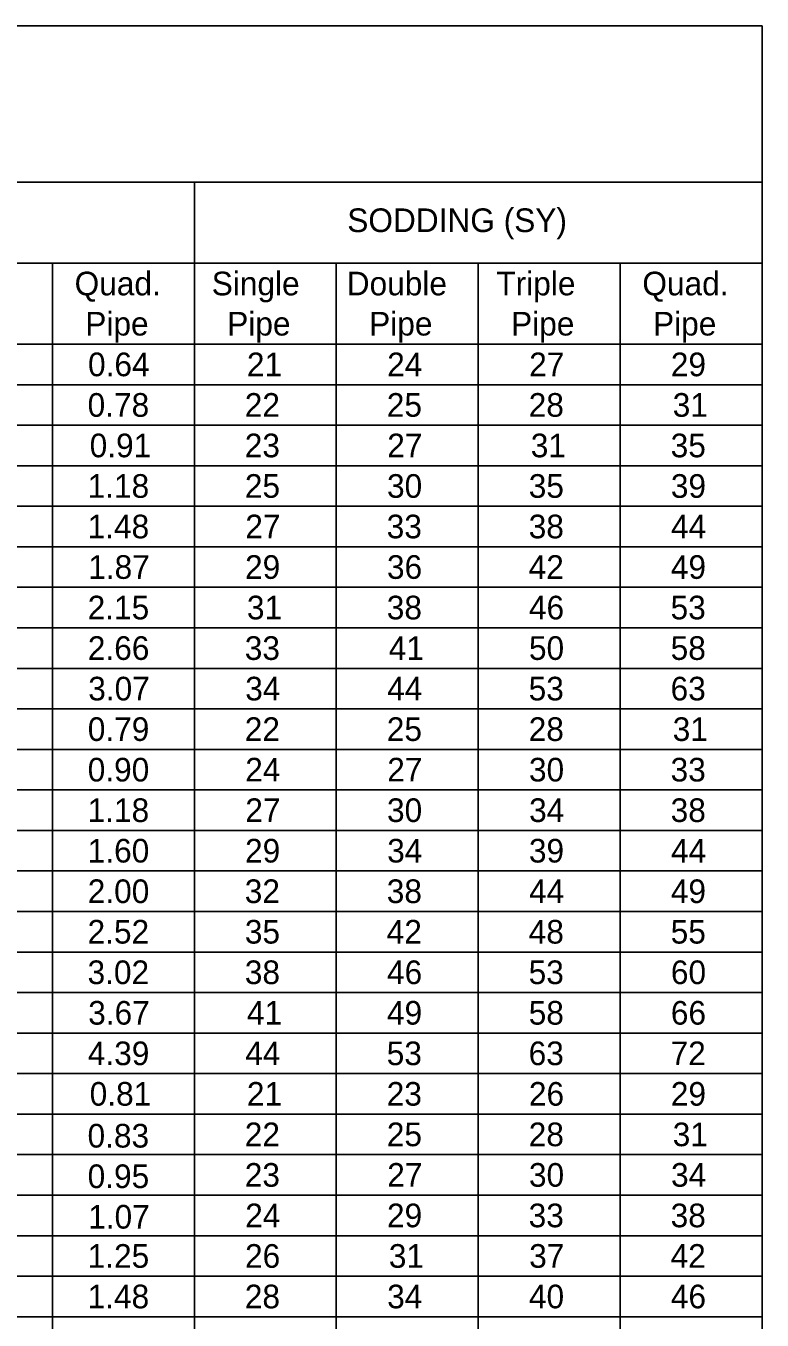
# Model space of a CAD drawing. Extents: x 1.7 to 14.4, y 0 to 7.8.
# Drawn here: x 11.282 to 13.46, y 3.92 to 7.752 of the extents above; entities that cross this region are included whole.
import ezdxf

# ---------------------------------------------------------------- set-up
doc = ezdxf.new("R2010")
doc.units = 0
doc.layers.add('Table', color=7, linetype='Continuous')

msp = doc.modelspace()

# ---------------------------------------------------------------- linework, layer by layer
at = {"layer": 'Table'}
msp.add_line((1.94, 7.7524), (13.46, 7.7524), dxfattribs=at)
for points in [[(13.46, 7.7524), (13.46, 7.17), (13.46, 6.81), (13.46, 6.69), (13.46, 6.57), (13.46, 6.45), (13.46, 6.33), (13.46, 6.21), (13.46, 6.09), (13.46, 5.97), (13.46, 5.85), (13.46, 5.73), (13.46, 5.61), (13.46, 5.49), (13.46, 5.37), (13.46, 5.25), (13.46, 5.13), (13.46, 5.01), (13.46, 4.89), (13.46, 4.77), (13.46, 4.65), (13.46, 4.53), (13.46, 4.41), (13.46, 4.29), (13.46, 4.17), (13.46, 4.05), (13.46, 3.93), (13.46, 3.81)], [(13.46, 7.29), (11.78, 7.29), (10.1, 7.29), (8.42, 7.29), (8.06, 7.29), (6.38, 7.29), (6.02, 7.29), (5.66, 7.29), (5.3, 7.29), (4.94, 7.29), (4.52, 7.29), (4.04, 7.29), (3.62, 7.29), (3.2, 7.29), (2.9, 7.29), (2.6, 7.29), (2.3, 7.29), (1.94, 7.29)], [(11.78, 7.29), (11.78, 6.81), (11.78, 6.69), (11.78, 6.57), (11.78, 6.45), (11.78, 6.33), (11.78, 6.21), (11.78, 6.09), (11.78, 5.97), (11.78, 5.85), (11.78, 5.73), (11.78, 5.61), (11.78, 5.49), (11.78, 5.37), (11.78, 5.25), (11.78, 5.13), (11.78, 5.01), (11.78, 4.89), (11.78, 4.77), (11.78, 4.65), (11.78, 4.53), (11.78, 4.41), (11.78, 4.29), (11.78, 4.17), (11.78, 4.05), (11.78, 3.93), (11.78, 3.81)], [(8.42, 7.05), (8.84, 7.05), (9.26, 7.05), (9.68, 7.05), (10.1, 7.05), (10.52, 7.05), (10.94, 7.05), (11.36, 7.05), (11.78, 7.05), (12.2, 7.05), (12.62, 7.05), (13.04, 7.05), (13.46, 7.05)], [(11.36, 7.05), (11.36, 6.81), (11.36, 6.69), (11.36, 6.57), (11.36, 6.45), (11.36, 6.33), (11.36, 6.21), (11.36, 6.09), (11.36, 5.97), (11.36, 5.85), (11.36, 5.73), (11.36, 5.61), (11.36, 5.49), (11.36, 5.37), (11.36, 5.25), (11.36, 5.13), (11.36, 5.01), (11.36, 4.89), (11.36, 4.77), (11.36, 4.65), (11.36, 4.53), (11.36, 4.41), (11.36, 4.29), (11.36, 4.17), (11.36, 4.05), (11.36, 3.93), (11.36, 3.81)], [(12.2, 7.05), (12.2, 6.81), (12.2, 6.69), (12.2, 6.57), (12.2, 6.45), (12.2, 6.33), (12.2, 6.21), (12.2, 6.09), (12.2, 5.97), (12.2, 5.85), (12.2, 5.73), (12.2, 5.61), (12.2, 5.49), (12.2, 5.37), (12.2, 5.25), (12.2, 5.13), (12.2, 5.01), (12.2, 4.89), (12.2, 4.77), (12.2, 4.65), (12.2, 4.53), (12.2, 4.41), (12.2, 4.29), (12.2, 4.17), (12.2, 4.05), (12.2, 3.93), (12.2, 3.81)], [(12.62, 7.05), (12.62, 6.81), (12.62, 6.69), (12.62, 6.57), (12.62, 6.45), (12.62, 6.33), (12.62, 6.21), (12.62, 6.09), (12.62, 5.97), (12.62, 5.85), (12.62, 5.73), (12.62, 5.61), (12.62, 5.49), (12.62, 5.37), (12.62, 5.25), (12.62, 5.13), (12.62, 5.01), (12.62, 4.89), (12.62, 4.77), (12.62, 4.65), (12.62, 4.53), (12.62, 4.41), (12.62, 4.29), (12.62, 4.17), (12.62, 4.05), (12.62, 3.93), (12.62, 3.81)], [(13.04, 7.05), (13.04, 6.81), (13.04, 6.69), (13.04, 6.57), (13.04, 6.45), (13.04, 6.33), (13.04, 6.21), (13.04, 6.09), (13.04, 5.97), (13.04, 5.85), (13.04, 5.73), (13.04, 5.61), (13.04, 5.49), (13.04, 5.37), (13.04, 5.25), (13.04, 5.13), (13.04, 5.01), (13.04, 4.89), (13.04, 4.77), (13.04, 4.65), (13.04, 4.53), (13.04, 4.41), (13.04, 4.29), (13.04, 4.17), (13.04, 4.05), (13.04, 3.93), (13.04, 3.81)], [(8.06, 6.81), (8.42, 6.81), (8.84, 6.81), (9.26, 6.81), (9.68, 6.81), (10.1, 6.81), (10.52, 6.81), (10.94, 6.81), (11.36, 6.81), (11.78, 6.81), (12.2, 6.81), (12.62, 6.81), (13.04, 6.81), (13.46, 6.81)], [(8.06, 6.69), (8.42, 6.69), (8.84, 6.69), (9.26, 6.69), (9.68, 6.69), (10.1, 6.69), (10.52, 6.69), (10.94, 6.69), (11.36, 6.69), (11.78, 6.69), (12.2, 6.69), (12.62, 6.69), (13.04, 6.69), (13.46, 6.69)], [(8.06, 6.57), (8.42, 6.57), (8.84, 6.57), (9.26, 6.57), (9.68, 6.57), (10.1, 6.57), (10.52, 6.57), (10.94, 6.57), (11.36, 6.57), (11.78, 6.57), (12.2, 6.57), (12.62, 6.57), (13.04, 6.57), (13.46, 6.57)], [(8.06, 6.45), (8.42, 6.45), (8.84, 6.45), (9.26, 6.45), (9.68, 6.45), (10.1, 6.45), (10.52, 6.45), (10.94, 6.45), (11.36, 6.45), (11.78, 6.45), (12.2, 6.45), (12.62, 6.45), (13.04, 6.45), (13.46, 6.45)], [(8.06, 6.33), (8.42, 6.33), (8.84, 6.33), (9.26, 6.33), (9.68, 6.33), (10.1, 6.33), (10.52, 6.33), (10.94, 6.33), (11.36, 6.33), (11.78, 6.33), (12.2, 6.33), (12.62, 6.33), (13.04, 6.33), (13.46, 6.33)], [(8.06, 6.21), (8.42, 6.21), (8.84, 6.21), (9.26, 6.21), (9.68, 6.21), (10.1, 6.21), (10.52, 6.21), (10.94, 6.21), (11.36, 6.21), (11.78, 6.21), (12.2, 6.21), (12.62, 6.21), (13.04, 6.21), (13.46, 6.21)], [(8.06, 6.09), (8.42, 6.09), (8.84, 6.09), (9.26, 6.09), (9.68, 6.09), (10.1, 6.09), (10.52, 6.09), (10.94, 6.09), (11.36, 6.09), (11.78, 6.09), (12.2, 6.09), (12.62, 6.09), (13.04, 6.09), (13.46, 6.09)], [(8.06, 5.97), (8.42, 5.97), (8.84, 5.97), (9.26, 5.97), (9.68, 5.97), (10.1, 5.97), (10.52, 5.97), (10.94, 5.97), (11.36, 5.97), (11.78, 5.97), (12.2, 5.97), (12.62, 5.97), (13.04, 5.97), (13.46, 5.97)], [(8.06, 5.85), (8.42, 5.85), (8.84, 5.85), (9.26, 5.85), (9.68, 5.85), (10.1, 5.85), (10.52, 5.85), (10.94, 5.85), (11.36, 5.85), (11.78, 5.85), (12.2, 5.85), (12.62, 5.85), (13.04, 5.85), (13.46, 5.85)], [(8.06, 5.73), (8.42, 5.73), (8.84, 5.73), (9.26, 5.73), (9.68, 5.73), (10.1, 5.73), (10.52, 5.73), (10.94, 5.73), (11.36, 5.73), (11.78, 5.73), (12.2, 5.73), (12.62, 5.73), (13.04, 5.73), (13.46, 5.73)], [(8.06, 5.61), (8.42, 5.61), (8.84, 5.61), (9.26, 5.61), (9.68, 5.61), (10.1, 5.61), (10.52, 5.61), (10.94, 5.61), (11.36, 5.61), (11.78, 5.61), (12.2, 5.61), (12.62, 5.61), (13.04, 5.61), (13.46, 5.61)], [(8.06, 5.49), (8.42, 5.49), (8.84, 5.49), (9.26, 5.49), (9.68, 5.49), (10.1, 5.49), (10.52, 5.49), (10.94, 5.49), (11.36, 5.49), (11.78, 5.49), (12.2, 5.49), (12.62, 5.49), (13.04, 5.49), (13.46, 5.49)], [(8.06, 5.37), (8.42, 5.37), (8.84, 5.37), (9.26, 5.37), (9.68, 5.37), (10.1, 5.37), (10.52, 5.37), (10.94, 5.37), (11.36, 5.37), (11.78, 5.37), (12.2, 5.37), (12.62, 5.37), (13.04, 5.37), (13.46, 5.37)], [(8.06, 5.25), (8.42, 5.25), (8.84, 5.25), (9.26, 5.25), (9.68, 5.25), (10.1, 5.25), (10.52, 5.25), (10.94, 5.25), (11.36, 5.25), (11.78, 5.25), (12.2, 5.25), (12.62, 5.25), (13.04, 5.25), (13.46, 5.25)], [(8.06, 5.13), (8.42, 5.13), (8.84, 5.13), (9.26, 5.13), (9.68, 5.13), (10.1, 5.13), (10.52, 5.13), (10.94, 5.13), (11.36, 5.13), (11.78, 5.13), (12.2, 5.13), (12.62, 5.13), (13.04, 5.13), (13.46, 5.13)], [(8.06, 5.01), (8.42, 5.01), (8.84, 5.01), (9.26, 5.01), (9.68, 5.01), (10.1, 5.01), (10.52, 5.01), (10.94, 5.01), (11.36, 5.01), (11.78, 5.01), (12.2, 5.01), (12.62, 5.01), (13.04, 5.01), (13.46, 5.01)], [(8.06, 4.89), (8.42, 4.89), (8.84, 4.89), (9.26, 4.89), (9.68, 4.89), (10.1, 4.89), (10.52, 4.89), (10.94, 4.89), (11.36, 4.89), (11.78, 4.89), (12.2, 4.89), (12.62, 4.89), (13.04, 4.89), (13.46, 4.89)], [(8.06, 4.77), (8.42, 4.77), (8.84, 4.77), (9.26, 4.77), (9.68, 4.77), (10.1, 4.77), (10.52, 4.77), (10.94, 4.77), (11.36, 4.77), (11.78, 4.77), (12.2, 4.77), (12.62, 4.77), (13.04, 4.77), (13.46, 4.77)], [(8.06, 4.65), (8.42, 4.65), (8.84, 4.65), (9.26, 4.65), (9.68, 4.65), (10.1, 4.65), (10.52, 4.65), (10.94, 4.65), (11.36, 4.65), (11.78, 4.65), (12.2, 4.65), (12.62, 4.65), (13.04, 4.65), (13.46, 4.65)], [(8.06, 4.53), (8.42, 4.53), (8.84, 4.53), (9.26, 4.53), (9.68, 4.53), (10.1, 4.53), (10.52, 4.53), (10.94, 4.53), (11.36, 4.53), (11.78, 4.53), (12.2, 4.53), (12.62, 4.53), (13.04, 4.53), (13.46, 4.53)], [(13.46, 3.69), (13.46, 4.53), (13.46, 4.41), (13.46, 4.29), (13.46, 4.17), (13.46, 4.05), (13.46, 3.93), (13.46, 3.81)], [(8.06, 4.41), (8.42, 4.41), (8.84, 4.41), (9.26, 4.41), (9.68, 4.41), (10.1, 4.41), (10.52, 4.41), (10.94, 4.41), (11.36, 4.41), (11.78, 4.41), (12.2, 4.41), (12.62, 4.41), (13.04, 4.41), (13.46, 4.41)], [(8.06, 4.29), (8.42, 4.29), (8.84, 4.29), (9.26, 4.29), (9.68, 4.29), (10.1, 4.29), (10.52, 4.29), (10.94, 4.29), (11.36, 4.29), (11.78, 4.29), (12.2, 4.29), (12.62, 4.29), (13.04, 4.29), (13.46, 4.29)], [(8.06, 4.17), (8.42, 4.17), (8.84, 4.17), (9.26, 4.17), (9.68, 4.17), (10.1, 4.17), (10.52, 4.17), (10.94, 4.17), (11.36, 4.17), (11.78, 4.17), (12.2, 4.17), (12.62, 4.17), (13.04, 4.17), (13.46, 4.17)], [(8.06, 4.05), (8.42, 4.05), (8.84, 4.05), (9.26, 4.05), (9.68, 4.05), (10.1, 4.05), (10.52, 4.05), (10.94, 4.05), (11.36, 4.05), (11.78, 4.05), (12.2, 4.05), (12.62, 4.05), (13.04, 4.05), (13.46, 4.05)], [(8.06, 3.93), (8.42, 3.93), (8.84, 3.93), (9.26, 3.93), (9.68, 3.93), (10.1, 3.93), (10.52, 3.93), (10.94, 3.93), (11.36, 3.93), (11.78, 3.93), (12.2, 3.93), (12.62, 3.93), (13.04, 3.93), (13.46, 3.93)]]:
    msp.add_lwpolyline(points, dxfattribs=at)

# ---------------------------------------------------------------- texts
for s, p in [('SODDING (SY)', (12.2325, 7.1419)), ('Quad.', (11.4257, 6.9545)), ('Single', (11.8314, 6.9545)), ('Double', (12.2309, 6.9545)), ('Triple', (12.6737, 6.9545)), ('Quad.', (13.1057, 6.9545)), ('Pipe', (11.4573, 6.8355)), ('Pipe', (11.8773, 6.8355)), ('Pipe', (12.2973, 6.8355)), ('Pipe', (12.7173, 6.8355)), ('Pipe', (13.1373, 6.8355)), ('0.64', (11.4654, 6.715)), ('0.78', (11.4642, 6.595)), ('0.91', (11.4703, 6.475)), ('1.18', (11.4642, 6.355)), ('1.48', (11.4642, 6.235)), ('1.87', (11.466, 6.115)), ('2.15', (11.4643, 5.995)), ('2.66', (11.4648, 5.875)), ('3.07', (11.466, 5.755)), ('0.79', (11.4647, 5.635)), ('0.90', (11.4645, 5.515)), ('1.18', (11.4642, 5.395)), ('1.60', (11.4645, 5.275)), ('2.00', (11.4646, 5.155)), ('2.52', (11.4641, 5.035)), ('3.02', (11.464, 4.915)), ('3.67', (11.4659, 4.795)), ('4.39', (11.4648, 4.675)), ('0.81', (11.4703, 4.555)), ('0.83', (11.464, 4.431)), ('0.95', (11.4643, 4.311)), ('1.07', (11.4659, 4.191)), ('1.25', (11.4643, 4.075)), ('1.48', (11.4642, 3.955))]:
    msp.add_text(s, height=0.07, dxfattribs=at).set_placement(p)
for s, p in [('21', (11.9355, 6.715)), ('24', (12.3506, 6.715)), ('27', (12.7708, 6.715)), ('29', (13.19, 6.715)), ('22', (11.9292, 6.595)), ('25', (12.3495, 6.595)), ('28', (12.7694, 6.595)), ('31', (13.1955, 6.595)), ('23', (11.9292, 6.475)), ('27', (12.3508, 6.475)), ('31', (12.7755, 6.475)), ('35', (13.1895, 6.475)), ('25', (11.9295, 6.355)), ('30', (12.3501, 6.355)), ('35', (12.7695, 6.355)), ('39', (13.19, 6.355)), ('27', (11.9308, 6.235)), ('33', (12.3492, 6.235)), ('38', (12.7694, 6.235)), ('44', (13.1906, 6.235)), ('29', (11.93, 6.115)), ('36', (12.35, 6.115)), ('42', (12.7692, 6.115)), ('49', (13.19, 6.115)), ('31', (11.9355, 5.995)), ('38', (12.3494, 5.995)), ('46', (12.77, 5.995)), ('53', (13.1892, 5.995)), ('33', (11.9292, 5.875)), ('41', (12.3555, 5.875)), ('50', (12.7701, 5.875)), ('58', (13.1894, 5.875)), ('34', (11.9306, 5.755)), ('53', (12.7692, 5.755)), ('63', (13.1892, 5.755)), ('44', (12.3506, 5.755)), ('22', (11.9292, 5.635)), ('25', (12.3495, 5.635)), ('28', (12.7694, 5.635)), ('31', (13.1955, 5.635)), ('24', (11.9306, 5.515)), ('27', (12.3508, 5.515)), ('30', (12.7701, 5.515)), ('33', (13.1892, 5.515)), ('27', (11.9308, 5.395)), ('30', (12.3501, 5.395)), ('34', (12.7706, 5.395)), ('38', (13.1894, 5.395)), ('29', (11.93, 5.275)), ('34', (12.3506, 5.275)), ('39', (12.77, 5.275)), ('44', (13.1906, 5.275)), ('32', (11.9292, 5.155)), ('38', (12.3494, 5.155)), ('44', (12.7706, 5.155)), ('49', (13.19, 5.155)), ('35', (11.9295, 5.035)), ('42', (12.3492, 5.035)), ('48', (12.7694, 5.035)), ('55', (13.1895, 5.035)), ('38', (11.9294, 4.915)), ('46', (12.35, 4.915)), ('53', (12.7692, 4.915)), ('60', (13.1901, 4.915)), ('41', (11.9355, 4.795)), ('49', (12.35, 4.795)), ('58', (12.7694, 4.795)), ('66', (13.19, 4.795)), ('44', (11.9306, 4.675)), ('53', (12.3492, 4.675)), ('63', (12.7692, 4.675)), ('72', (13.1892, 4.675)), ('21', (11.9355, 4.555)), ('23', (12.3492, 4.555)), ('26', (12.77, 4.555)), ('29', (13.19, 4.555)), ('22', (11.9292, 4.435)), ('25', (12.3495, 4.435)), ('28', (12.7694, 4.435)), ('31', (13.1955, 4.435)), ('23', (11.9292, 4.315)), ('27', (12.3508, 4.315)), ('30', (12.7701, 4.315)), ('34', (13.1906, 4.315)), ('24', (11.9306, 4.195)), ('29', (12.35, 4.195)), ('33', (12.7692, 4.195)), ('38', (13.1894, 4.195)), ('26', (11.93, 4.075)), ('31', (12.3555, 4.075)), ('37', (12.7708, 4.075)), ('42', (13.1892, 4.075)), ('28', (11.9294, 3.955)), ('34', (12.3506, 3.955)), ('40', (12.7701, 3.955)), ('46', (13.19, 3.955))]:
    msp.add_text(s, height=0.07, rotation=0, dxfattribs=at).set_placement(p)

doc.saveas('drawing.dxf')
